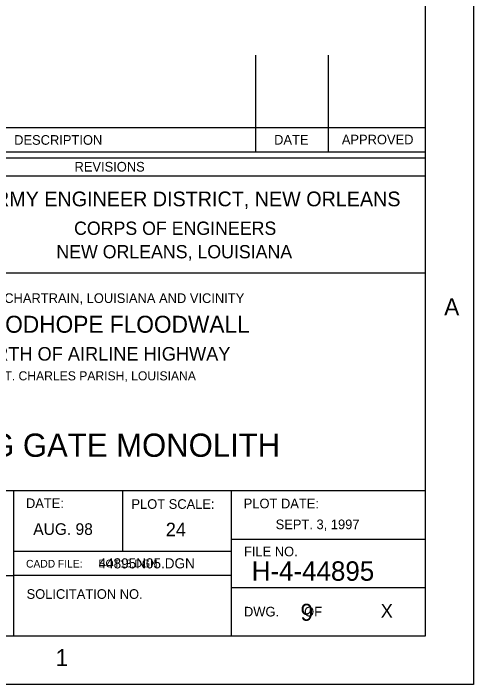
# Model space of a CAD drawing. Extents: x -11983 to -11903, y -13969.5 to -13913.5.
# Drawn here: x -11912.52 to -11903.01, y -13969.48 to -13955.62 of the extents above; entities that cross this region are included whole.
import ezdxf

# ---------------------------------------------------------------- set-up
doc = ezdxf.new("R2010")
doc.units = 0
for name, color, linetype in [('Level 1', 7, 'Continuous'), ('Level 2', 7, 'Continuous'), ('Level 22', 7, 'Continuous')]:
    doc.layers.add(name, color=color, linetype=linetype)

msp = doc.modelspace()

# ---------------------------------------------------------------- linework, layer by layer
at = {"layer": 'Level 1'}
for p, q in [((-11907.512, -13958.481), (-11907.512, -13956.481)), ((-11906.012, -13958.481), (-11906.012, -13956.481)), ((-11904.012, -13957.981), (-11917.012, -13957.981)), ((-11904.012, -13958.481), (-11917.012, -13958.481)), ((-11904.012, -13958.606), (-11917.012, -13958.606)), ((-11904.012, -13958.981), (-11917.012, -13958.981)), ((-11904.012, -13960.981), (-11917.012, -13960.981)), ((-11904.012, -13965.481), (-11917.012, -13965.481)), ((-11912.512, -13968.481), (-11912.512, -13965.481)), ((-11910.262, -13966.731), (-11910.262, -13965.481)), ((-11908.012, -13968.481), (-11908.012, -13965.481)), ((-11904.012, -13966.481), (-11908.012, -13966.481)), ((-11908.012, -13966.731), (-11912.512, -13966.731)), ((-11917.012, -13967.231), (-11912.512, -13967.231)), ((-11908.012, -13967.231), (-11912.512, -13967.231)), ((-11904.012, -13967.481), (-11908.012, -13967.481))]:
    msp.add_line(p, q, dxfattribs=at)
for points in [[(-11983.012, -13913.481), (-11903.012, -13913.481), (-11903.012, -13969.481), (-11983.012, -13969.481)], [(-11980.012, -13914.481), (-11904.012, -13914.481), (-11904.012, -13968.481), (-11980.012, -13968.481)]]:
    msp.add_lwpolyline(points, close=True, dxfattribs=at)

# ---------------------------------------------------------------- texts
for s, height, p in [('DESCRIPTION', 0.19925, (-11912.504, -13958.33)), ('DATE', 0.1992, (-11907.133, -13958.326)), ('APPROVED', 0.1992, (-11905.734, -13958.321)), ('REVISIONS', 0.1992, (-11911.257, -13958.883)), ('U.S. ARMY ENGINEER DISTRICT, NEW ORLEANS', 0.30475, (-11914.077, -13959.601)), ('CORPS OF ENGINEERS', 0.27428, (-11911.266, -13960.191)), ('NEW ORLEANS, LOUISIANA', 0.27428, (-11911.632, -13960.676)), ('A', 0.351, (-11903.62, -13961.854)), ('DATE:', 0.1992, (-11912.26, -13965.834)), ('PLOT SCALE:', 0.19925, (-11910.081, -13965.851)), ('PLOT DATE:', 0.1992, (-11907.761, -13965.84)), ('FILE NO.', 0.1992, (-11907.756, -13966.831)), ('CADD FILE:', 0.1585, (-11912.258, -13967.064)), ('SOLICITATION NO.', 0.19925, (-11912.247, -13967.71)), ('DWG.       OF', 0.19925, (-11907.756, -13968.074)), ('1', 0.351, (-11911.647, -13969.099))]:
    msp.add_text(s, height=height, dxfattribs=at).set_placement(p)
at = {"layer": 'Level 2'}
for s, height, p in [('LAKE PONTCHARTRAIN, LOUISIANA AND VICINITY', 0.19925, (-11914.204, -13961.598)), ('GOODHOPE FLOODWALL', 0.3505, (-11913.418, -13962.213)), ('NORTH OF AIRLINE HIGHWAY', 0.28075, (-11913.459, -13962.789)), ('ST. CHARLES PARISH, LOUISIANA', 0.1875, (-11912.873, -13963.197)), ('SWING GATE MONOLITH', 0.48009, (-11914.677, -13964.776)), ('AUG. 98', 0.24, (-11912.109, -13966.389)), ('AUG. 98', 0.24, (-11912.109, -13966.389)), ('AUG. 98', 0.24, (-11912.109, -13966.389)), ('SEPT. 3, 1997', 0.19919, (-11907.101, -13966.271)), ('44895N05.DGN', 0.209, (-11910.76, -13967.081)), ('BOT13.DGN', 0.1608, (-11910.76, -13967.06)), ('H-4-44895', 0.4007, (-11907.597, -13967.336)), ('9', 0.351, (-11906.589, -13968.163)), ('X', 0.281, (-11904.931, -13968.1))]:
    msp.add_text(s, height=height, dxfattribs=at).set_placement(p)
at = {"layer": 'Level 22'}
msp.add_text('24', height=0.2808, dxfattribs=at).set_placement((-11909.371, -13966.418))

doc.saveas('drawing.dxf')
